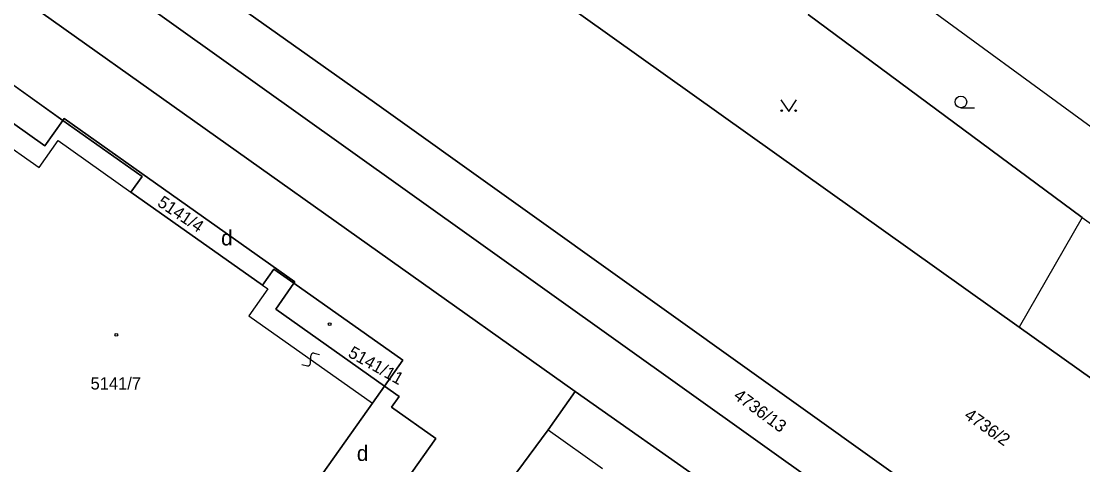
# Model space of a CAD drawing. Extents: x -400488 to -400124, y -1251493 to -1251223.
# Drawn here: x -400324.23 to -400282.93, y -1251297.01 to -1251279.74 of the extents above; entities that cross this region are included whole.
import ezdxf

# ---------------------------------------------------------------- set-up
doc = ezdxf.new("R2010")
doc.units = 0
doc.layers.add('Level 63', color=7, linetype='Continuous')

msp = doc.modelspace()

# ---------------------------------------------------------------- linework, layer by layer
at = {"layer": 'Level 63'}
for p, q in [((-400341.55, -1251266.53), (-400302.68, -1251294.16)), ((-400302.68, -1251294.16), (-400341.55, -1251266.53)), ((-400327.86, -1251270.56), (-400310.49, -1251282.91)), ((-400310.49, -1251282.91), (-400327.86, -1251270.56)), ((-400311.69, -1251284.59), (-400325.55, -1251274.7)), ((-400325.55, -1251274.7), (-400311.69, -1251284.59)), ((-400285.41, -1251291.65), (-400304.78, -1251277.83)), ((-400304.78, -1251277.83), (-400285.41, -1251291.65)), ((-400291.07, -1251277.65), (-400282.6, -1251283.85)), ((-400282.95, -1251287.38), (-400293.61, -1251279.48)), ((-400293.61, -1251279.48), (-400282.95, -1251287.38)), ((-400322.61, -1251283.6), (-400327.73, -1251279.97)), ((-400327.73, -1251279.97), (-400322.61, -1251283.6)), ((-400323.31, -1251284.59), (-400327.59, -1251281.56)), ((-400327.59, -1251281.56), (-400323.31, -1251284.59)), ((-400327.84, -1251282.41), (-400323.53, -1251285.44)), ((-400310.49, -1251282.91), (-400289.76, -1251297.72)), ((-400289.76, -1251297.72), (-400310.49, -1251282.91)), ((-400294.67, -1251282.8), (-400294.37, -1251283.25)), ((-400294.37, -1251283.25), (-400294.07, -1251282.8)), ((-400287.67, -1251283.11), (-400287.145, -1251283.11)), ((-400322.61, -1251283.6), (-400323.31, -1251284.59)), ((-400323.31, -1251284.59), (-400322.61, -1251283.6)), ((-400322.56, -1251283.53), (-400322.61, -1251283.6)), ((-400322.61, -1251283.6), (-400322.56, -1251283.53)), ((-400319.53, -1251285.78), (-400322.61, -1251283.6)), ((-400322.61, -1251283.6), (-400319.53, -1251285.78)), ((-400313.58, -1251289.89), (-400322.56, -1251283.53)), ((-400322.56, -1251283.53), (-400313.58, -1251289.89)), ((-400323.53, -1251285.44), (-400322.79, -1251284.38)), ((-400322.79, -1251284.38), (-400319.96, -1251286.39)), ((-400290.91, -1251299.42), (-400311.69, -1251284.59)), ((-400311.69, -1251284.59), (-400290.91, -1251299.42)), ((-400319.96, -1251286.39), (-400319.53, -1251285.78)), ((-400319.53, -1251285.78), (-400319.96, -1251286.39)), ((-400314.84, -1251290.02), (-400319.96, -1251286.39)), ((-400319.96, -1251286.39), (-400314.84, -1251290.02)), ((-400282.95, -1251287.38), (-400285.41, -1251291.65)), ((-400282.95, -1251287.38), (-400274.607, -1251293.448)), ((-400314.4, -1251289.39), (-400314.84, -1251290.02)), ((-400314.84, -1251290.02), (-400314.4, -1251289.39)), ((-400313.62, -1251289.94), (-400314.4, -1251289.39)), ((-400314.4, -1251289.39), (-400313.62, -1251289.94)), ((-400314.33, -1251290.95), (-400313.62, -1251289.94)), ((-400313.62, -1251289.94), (-400314.33, -1251290.95)), ((-400313.62, -1251289.94), (-400313.58, -1251289.89)), ((-400313.58, -1251289.89), (-400313.62, -1251289.94)), ((-400309.38, -1251292.94), (-400313.62, -1251289.94)), ((-400313.62, -1251289.94), (-400309.38, -1251292.94)), ((-400314.63, -1251290.16), (-400315.37, -1251291.21)), ((-400314.84, -1251290.02), (-400314.63, -1251290.16)), ((-400315.37, -1251291.21), (-400310.56, -1251294.61)), ((-400310.09, -1251293.95), (-400314.33, -1251290.95)), ((-400314.33, -1251290.95), (-400310.09, -1251293.95)), ((-400281.26, -1251294.6), (-400285.41, -1251291.65)), ((-400285.41, -1251291.65), (-400281.26, -1251294.6)), ((-400312.971, -1251293.057), (-400312.959, -1251292.763)), ((-400312.838, -1251292.669), (-400312.62, -1251292.717)), ((-400313.31, -1251293.103), (-400313.092, -1251293.151)), ((-400310.09, -1251293.95), (-400309.38, -1251292.94)), ((-400309.38, -1251292.94), (-400310.09, -1251293.95)), ((-400310.56, -1251294.61), (-400310.09, -1251293.95)), ((-400310.09, -1251293.95), (-400310.56, -1251294.61)), ((-400309.53, -1251294.35), (-400310.09, -1251293.95)), ((-400310.09, -1251293.95), (-400309.53, -1251294.35)), ((-400309.82, -1251294.76), (-400309.53, -1251294.35)), ((-400309.53, -1251294.35), (-400309.82, -1251294.76)), ((-400303.73, -1251295.65), (-400302.68, -1251294.16)), ((-400302.68, -1251294.16), (-400303.73, -1251295.65)), ((-400302.68, -1251294.16), (-400290.33, -1251302.83)), ((-400290.33, -1251302.83), (-400302.68, -1251294.16)), ((-400314.57, -1251300.27), (-400310.56, -1251294.61)), ((-400310.56, -1251294.61), (-400314.57, -1251300.27)), ((-400308.1, -1251295.98), (-400309.82, -1251294.76)), ((-400309.82, -1251294.76), (-400308.1, -1251295.98)), ((-400318.35, -1251315.34), (-400303.73, -1251295.65)), ((-400303.73, -1251295.65), (-400318.35, -1251315.34)), ((-400303.73, -1251295.65), (-400301.61, -1251297.15)), ((-400311.82, -1251301.22), (-400308.1, -1251295.98)), ((-400308.1, -1251295.98), (-400311.82, -1251301.22))]:
    msp.add_line(p, q, dxfattribs=at)
for centre, radius in [((-400287.67, -1251282.885), 0.225), ((-400294.64, -1251283.22), 0.03), ((-400294.1, -1251283.22), 0.03), ((-400312.23, -1251291.536), 0.054), ((-400320.53, -1251291.946), 0.054)]:
    msp.add_circle(centre, radius, dxfattribs=at)
for centre, start, end in [((-400312.859, -1251292.767), 77.7527, 177.7631), ((-400313.071, -1251293.053), 257.753, 357.7631)]:
    msp.add_arc(centre, 0.1, start, end, dxfattribs=at)

# ---------------------------------------------------------------- texts
for s, rotation, p in [('5141/4', 326.2073, (-400318.971, -1251286.899)), ('5141/11', 330.5601, (-400311.552, -1251292.779)), ('4736/13', 323.5236, (-400296.552, -1251294.4)), ('4736/2', 324.685, (-400287.578, -1251295.169))]:
    msp.add_text(s, height=0.48, rotation=rotation, dxfattribs=at).set_placement(p)
for s, height, p in [('d', 0.6, (-400316.453, -1251288.47)), ('5141/7', 0.48, (-400321.532, -1251294.08)), ('d', 0.6, (-400311.173, -1251296.86))]:
    msp.add_text(s, height=height, dxfattribs=at).set_placement(p)

doc.saveas('drawing.dxf')
